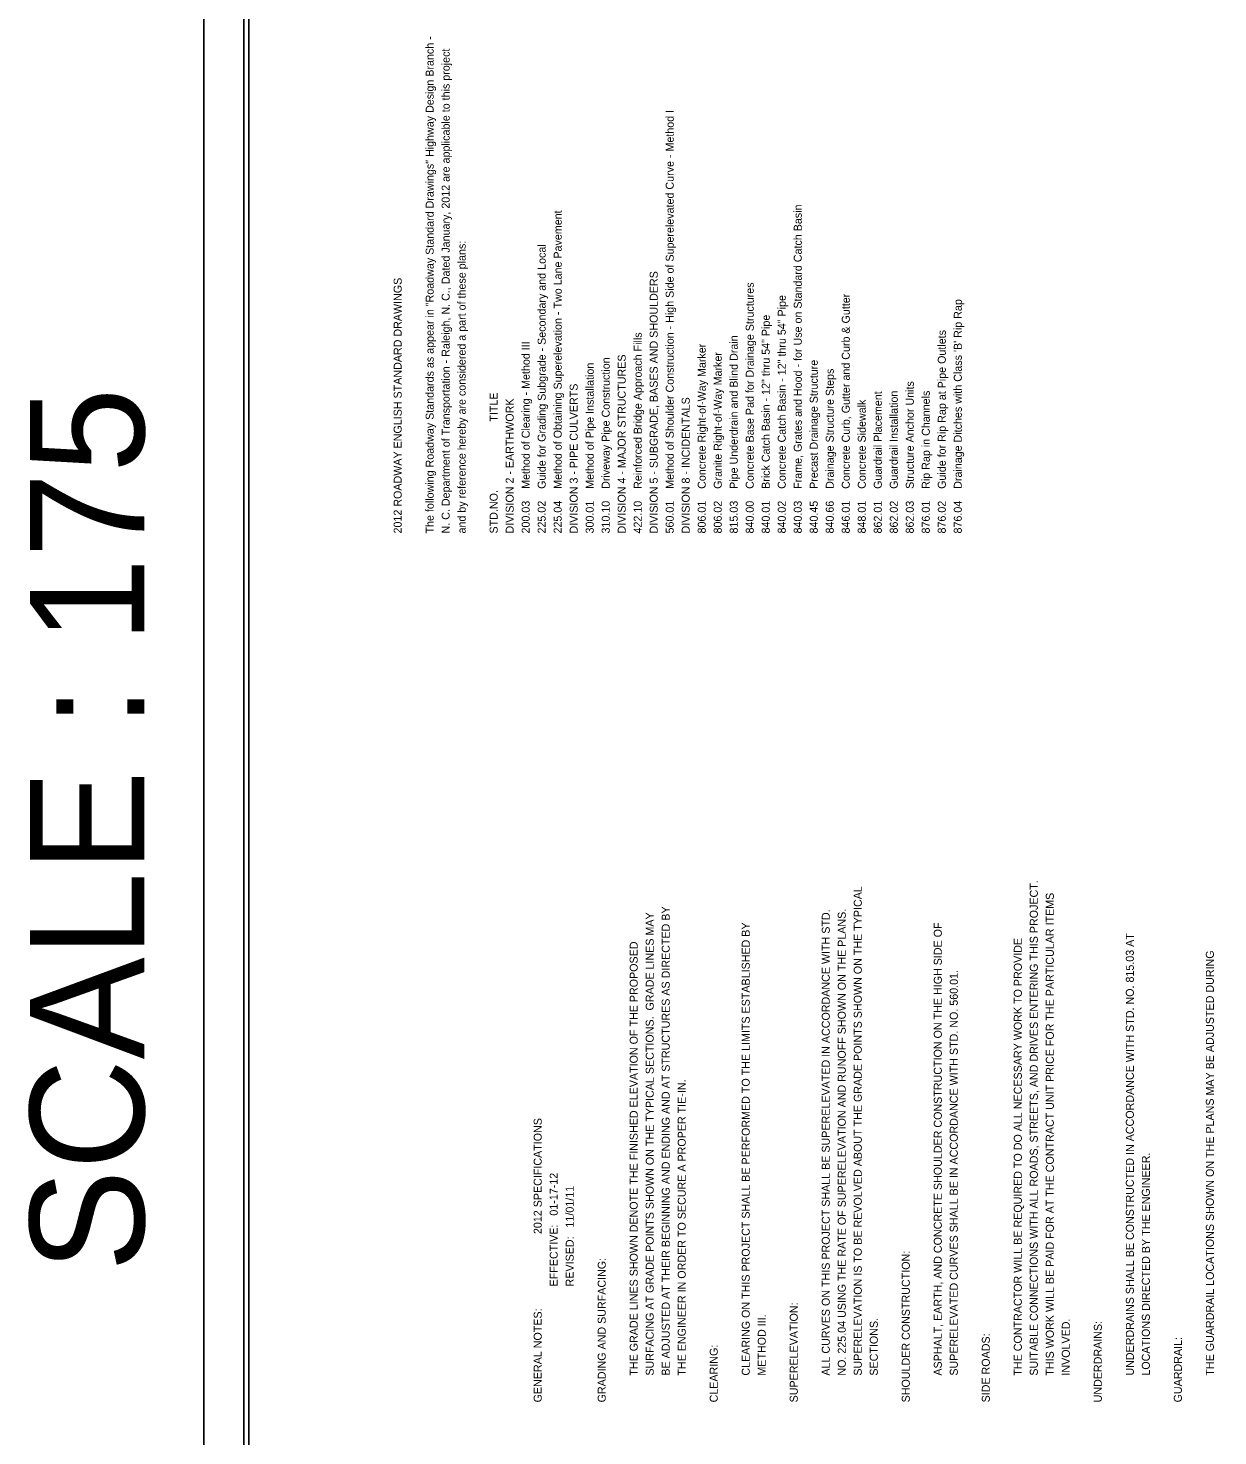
# Model space of a CAD drawing. Extents: x 2026893 to 2039781, y 729195 to 739590.
# Drawn here: x 2030935 to 2033017, y 735872 to 738335 of the extents above; entities that cross this region are included whole.
import ezdxf

# ---------------------------------------------------------------- set-up
doc = ezdxf.new("R2010")
doc.units = 0
for name, color, linetype in [('Old_Level_1', 7, 'Continuous'), ('Scratch_Level_3', 7, 'Continuous'), ('Sheet Cutting Line CELL', 7, 'Continuous'), ('Sheet Plan CELL', 7, 'Continuous'), ('Sheet Plot Border Inside CELL', 7, 'Continuous'), ('Sheet Plot Border Outside CELL', 7, 'Continuous')]:
    doc.layers.add(name, color=color, linetype=linetype)

msp = doc.modelspace()

# ---------------------------------------------------------------- linework, layer by layer
at = {"layer": 'Sheet Cutting Line CELL'}
msp.add_line((2031242.8, 739588.2), (2031242.8, 733695.9), dxfattribs=at)
at = {"layer": 'Sheet Plan CELL'}
msp.add_lwpolyline([(2031321.6, 739528.7), (2031321.6, 734278.7), (2034996.6, 734278.7), (2034996.6, 739528.7)], close=True, dxfattribs=at)
at = {"layer": 'Sheet Plot Border Inside CELL'}
msp.add_lwpolyline([(2035005.3, 733741.4), (2035005.3, 739572.4), (2031312.8, 739572.4), (2031312.8, 733741.4)], close=True, dxfattribs=at)
at = {"layer": 'Sheet Plot Border Outside CELL'}
msp.add_lwpolyline([(2035075.3, 733695.9), (2035075.3, 739588.2), (2031242.8, 739588.2), (2031242.8, 733695.9)], close=True, dxfattribs=at)

# ---------------------------------------------------------------- texts
at = {"layer": 'Old_Level_1'}
for s, height, p in [('The following Roadway Standards as appear in "Roadway Standard Drawings" Highway Design Branch -', 14, (2031644.9, 737450.8)), ('N. C. Department of Transportation - Raleigh, N. C., Dated January, 2012 are applicable to this project', 13.9999, (2031672.9, 737450.8)), ('560.01    Method of Shoulder Construction - High Side of Superelevated Curve - Method I', 14, (2032064.9, 737450.8)), ('225.04    Method of Obtaining Superelevation - Two Lane Pavement', 14, (2031868.9, 737450.8)), ('840.03    Frame, Grates and Hood - for Use on Standard Catch Basin', 14, (2032288.9, 737450.8)), ('and by reference hereby are considered a part of these plans:', 14, (2031700.9, 737450.8)), ('225.02    Guide for Grading Subgrade - Secondary and Local', 14, (2031840.9, 737450.8)), ('2012 ROADWAY ENGLISH STANDARD DRAWINGS', 14, (2031588.9, 737450.8)), ('DIVISION 5 - SUBGRADE, BASES AND SHOULDERS', 14, (2032036.9, 737450.8)), ('840.00    Concrete Base Pad for Drainage Structures', 14, (2032204.9, 737450.8)), ('840.02    Concrete Catch Basin - 12" thru 54" Pipe', 14, (2032260.9, 737450.8)), ('846.01    Concrete Curb, Gutter and Curb & Gutter', 14, (2032372.9, 737450.8)), ("876.04    Drainage Ditches with Class 'B' Rip Rap", 14, (2032568.9, 737450.8)), ('840.01    Brick Catch Basin - 12" thru 54" Pipe', 14, (2032232.9, 737450.8)), ('422.10    Reinforced Bridge Approach Fills', 14, (2032008.9, 737450.8)), ('815.03    Pipe Underdrain and Blind Drain', 14, (2032176.9, 737450.8)), ('876.02    Guide for Rip Rap at Pipe Outlets', 14, (2032540.9, 737450.8)), ('200.03    Method of Clearing - Method III', 14, (2031812.9, 737450.8)), ('806.01    Concrete Right-of-Way Marker', 14, (2032120.9, 737450.8)), ('806.02    Granite Right-of-Way Marker', 14, (2032148.9, 737450.8)), ('300.01    Method of Pipe Installation ', 14, (2031924.9, 737450.8)), ('310.10    Driveway Pipe Construction', 14, (2031952.9, 737450.8)), ('DIVISION 4 - MAJOR STRUCTURES', 14, (2031980.9, 737450.8)), ('840.45    Precast Drainage Structure', 14, (2032316.9, 737450.8)), ('840.66    Drainage Structure Steps', 14, (2032344.9, 737450.8)), ('STD.NO.                       TITLE', 14, (2031756.9, 737450.8)), ('DIVISION 3 - PIPE CULVERTS', 14, (2031896.9, 737450.8)), ('862.01    Guardrail Placement', 14, (2032428.9, 737450.8)), ('862.02    Guardrail Installation', 14, (2032456.9, 737450.8)), ('862.03    Structure Anchor Units', 14, (2032484.9, 737450.8)), ('876.01    Rip Rap in Channels', 14, (2032512.9, 737450.8)), ('DIVISION 2 - EARTHWORK', 14, (2031784.9, 737450.8)), ('DIVISION 8 - INCIDENTALS', 14, (2032092.9, 737450.8)), ('848.01    Concrete Sidewalk', 14, (2032400.9, 737450.8)), ('         SUPERELEVATION IS TO BE REVOLVED ABOUT THE GRADE POINTS SHOWN ON THE TYPICAL ', 14, (2032393.9, 735931)), ('         SUITABLE CONNECTIONS WITH ALL ROADS, STREETS, AND DRIVES ENTERING THIS PROJECT.  ', 14, (2032701.9, 735931)), ('         THIS WORK WILL BE PAID FOR AT THE CONTRACT UNIT PRICE FOR THE PARTICULAR ITEMS ', 14, (2032729.9, 735931)), ('         SURFACING AT GRADE POINTS SHOWN ON THE TYPICAL SECTIONS.  GRADE LINES MAY ', 14, (2032029.9, 735931)), ('         BE ADJUSTED AT THEIR BEGINNING AND ENDING AND AT STRUCTURES AS DIRECTED BY ', 14, (2032057.9, 735931)), ('         ALL CURVES ON THIS PROJECT SHALL BE SUPERELEVATED IN ACCORDANCE WITH STD. ', 14, (2032337.9, 735931)), ('         NO. 225.04 USING THE RATE OF SUPERELEVATION AND RUNOFF SHOWN ON THE PLANS.', 14, (2032365.9, 735931)), ('         CLEARING ON THIS PROJECT SHALL BE PERFORMED TO THE LIMITS ESTABLISHED BY ', 14, (2032197.9, 735931)), ('         ASPHALT, EARTH, AND CONCRETE SHOULDER CONSTRUCTION ON THE HIGH SIDE OF', 14, (2032533.9, 735931)), ('         THE GRADE LINES SHOWN DENOTE THE FINISHED ELEVATION OF THE PROPOSED ', 14, (2032001.9, 735931)), ('         THE CONTRACTOR WILL BE REQUIRED TO DO ALL NECESSARY WORK TO PROVIDE ', 14, (2032673.9, 735931)), ('         UNDERDRAINS SHALL BE CONSTRUCTED IN ACCORDANCE WITH STD. NO. 815.03 AT ', 14, (2032869.9, 735931)), ('         THE GUARDRAIL LOCATIONS SHOWN ON THE PLANS MAY BE ADJUSTED DURING ', 14, (2033009.9, 735931)), ('         SUPERELEVATED CURVES SHALL BE IN ACCORDANCE WITH STD. NO. 560.01.', 14, (2032561.9, 735931)), ('         THE ENGINEER IN ORDER TO SECURE A PROPER TIE-IN.  ', 14, (2032085.9, 735931)), ('GENERAL NOTES:                         2012 SPECIFICATIONS', 14, (2031833.9, 735931)), ('         LOCATIONS DIRECTED BY THE ENGINEER.  ', 14, (2032897.9, 735931)), ('                                       EFFECTIVE:   01-17-12', 14, (2031861.9, 735931)), ('                                       REVISED:   11/01/11', 14, (2031889.9, 735931)), ('SHOULDER CONSTRUCTION:  ', 14, (2032477.9, 735931)), ('GRADING AND SURFACING:  ', 14, (2031945.9, 735931)), ('SUPERELEVATION:  ', 14, (2032281.9, 735931)), ('         METHOD III.', 14, (2032225.9, 735931)), ('         SECTIONS.  ', 14, (2032421.9, 735931)), ('         INVOLVED.  ', 14, (2032757.9, 735931)), ('UNDERDRAINS:  ', 14, (2032813.9, 735931)), ('SIDE ROADS:  ', 14, (2032617.9, 735931)), ('GUARDRAIL:  ', 14, (2032953.9, 735931)), ('CLEARING:  ', 14, (2032141.9, 735931))]:
    msp.add_text(s, height=height, rotation=90, dxfattribs=at).set_placement(p)
at = {"layer": 'Scratch_Level_3'}
msp.add_text(' SCALE : 175', height=200, rotation=90, dxfattribs=at).set_placement((2031138.4, 736085.3))

doc.saveas('drawing.dxf')
